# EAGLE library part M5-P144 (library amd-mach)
AMD MACH SERIES
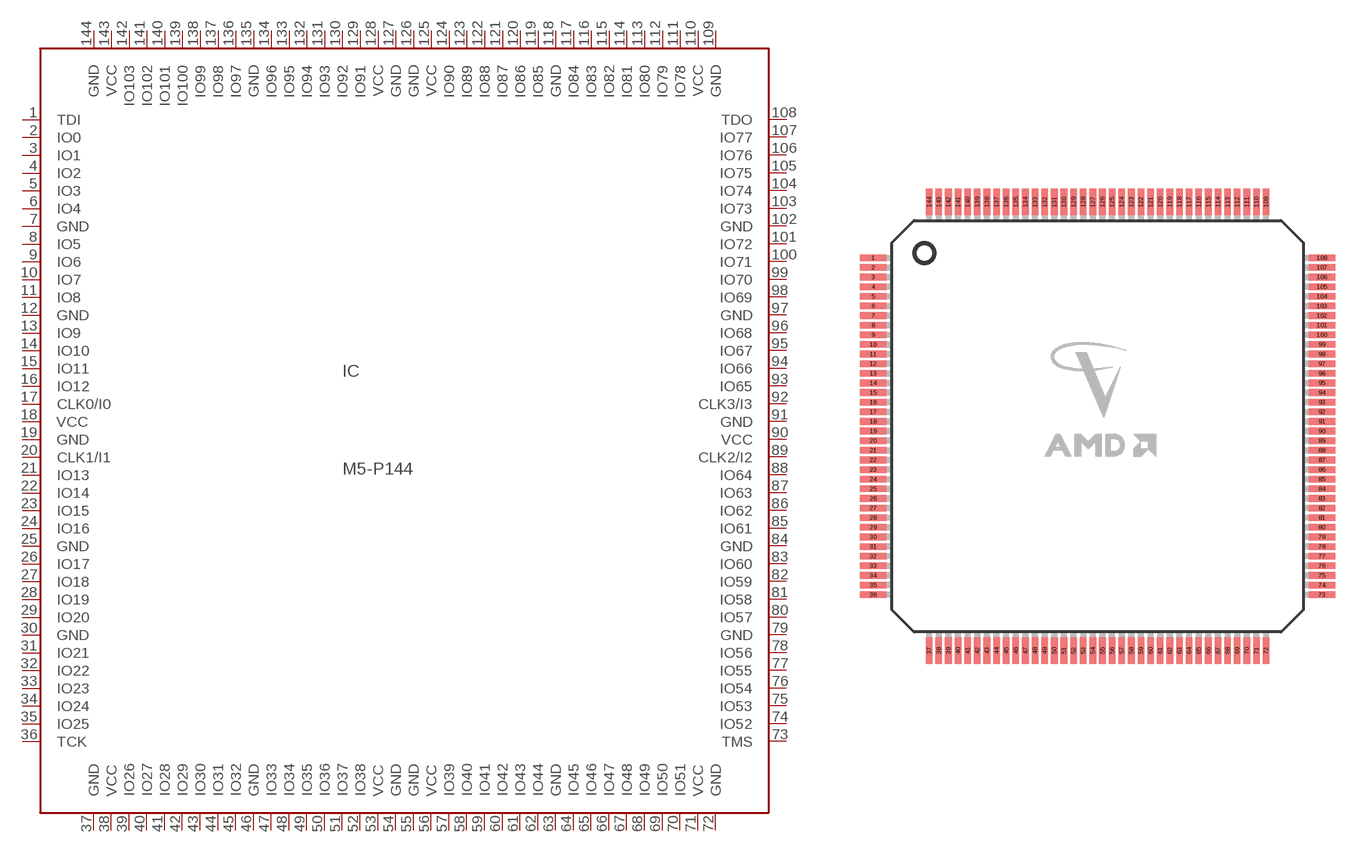
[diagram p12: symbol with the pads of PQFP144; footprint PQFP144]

Designator prefix IC

## M5-P144 (OC_FARNELL: unknown; OC_NEWARK: unknown)  [PQFP144]
1  TDI  in
2  IO0
3  IO1
4  IO2
5  IO3
6  IO4
7  GND  pwr
8  IO5
9  IO6
10  IO7
11  IO8
12  GND  pwr
13  IO9
14  IO10
15  IO11
16  IO12
17  CLK0/I0  in
18  VCC  pwr
19  GND  pwr
20  CLK1/I1  in
21  IO13
22  IO14
23  IO15
24  IO16
25  GND  pwr
26  IO17
27  IO18
28  IO19
29  IO20
30  GND  pwr
31  IO21
32  IO22
33  IO23
34  IO24
35  IO25
36  TCK  in
37  GND  pwr
38  VCC  pwr
39  IO26
40  IO27
41  IO28
42  IO29
43  IO30
44  IO31
45  IO32
46  GND  pwr
47  IO33
48  IO34
49  IO35
50  IO36
51  IO37
52  IO38
53  VCC  pwr
54  GND  pwr
55  GND  pwr
56  VCC  pwr
57  IO39
58  IO40
59  IO41
60  IO42
61  IO43
62  IO44
63  GND  pwr
64  IO45
65  IO46
66  IO47
67  IO48
68  IO49
69  IO50
70  IO51
71  VCC  pwr
72  GND  pwr
73  TMS  in
74  IO52
75  IO53
76  IO54
77  IO55
78  IO56
79  GND  pwr
80  IO57
81  IO58
82  IO59
83  IO60
84  GND  pwr
85  IO61
86  IO62
87  IO63
88  IO64
89  CLK2/I2  in
90  VCC  pwr
91  GND  pwr
92  CLK3/I3  in
93  IO65
94  IO66
95  IO67
96  IO68
97  GND  pwr
98  IO69
99  IO70
100  IO71
101  IO72
102  GND  pwr
103  IO73
104  IO74
105  IO75
106  IO76
107  IO77
108  TDO  out
109  GND  pwr
110  VCC  pwr
111  IO78
112  IO79
113  IO80
114  IO81
115  IO82
116  IO83
117  IO84
118  GND  pwr
119  IO85
120  IO86
121  IO87
122  IO88
123  IO89
124  IO90
125  VCC  pwr
126  GND  pwr
127  GND  pwr
128  VCC  pwr
129  IO91
130  IO92
131  IO93
132  IO94
133  IO95
134  IO96
135  GND  pwr
136  IO97
137  IO98
138  IO99
139  IO100
140  IO101
141  IO102
142  IO103
143  VCC  pwr
144  GND  pwr

## Footprint PQFP144 (pad centres in mm)
PLASTIC QUAD FLAT PACK
smd 1.8 x 0.45: 1 -15.15,11.375; 2 -15.15,10.725; 3 -15.15,10.075; 4 -15.15,9.425; 5 -15.15,8.775; 6 -15.15,8.125; 7 -15.15,7.475; 8 -15.15,6.825; 9 -15.15,6.175; 10 -15.15,5.525; 11 -15.15,4.875; 12 -15.15,4.225; 13 -15.15,3.575; 14 -15.15,2.925; 15 -15.15,2.275; 16 -15.15,1.625; 17 -15.15,0.975; 18 -15.15,0.325; 19 -15.15,-0.325; 20 -15.15,-0.975; 21 -15.15,-1.625; 22 -15.15,-2.275; 23 -15.15,-2.925; 24 -15.15,-3.575; 25 -15.15,-4.225; 26 -15.15,-4.875; 27 -15.15,-5.525; 28 -15.15,-6.175; 29 -15.15,-6.825; 30 -15.15,-7.475; 31 -15.15,-8.125; 32 -15.15,-8.775; 33 -15.15,-9.425; 34 -15.15,-10.075; 35 -15.15,-10.725; 36 -15.15,-11.375; 73 15.15,-11.375; 74 15.15,-10.725; 75 15.15,-10.075; 76 15.15,-9.425; 77 15.15,-8.775; 78 15.15,-8.125; 79 15.15,-7.475; 80 15.15,-6.825; 81 15.15,-6.175; 82 15.15,-5.525; 83 15.15,-4.875; 84 15.15,-4.225; 85 15.15,-3.575; 86 15.15,-2.925; 87 15.15,-2.275; 88 15.15,-1.625; 89 15.15,-0.975; 90 15.15,-0.325; 91 15.15,0.325; 92 15.15,0.975; 93 15.15,1.625; 94 15.15,2.275; 95 15.15,2.925; 96 15.15,3.575; 97 15.15,4.225; 98 15.15,4.875; 99 15.15,5.525; 100 15.15,6.175; 101 15.15,6.825; 102 15.15,7.475; 103 15.15,8.125; 104 15.15,8.775; 105 15.15,9.425; 106 15.15,10.075; 107 15.15,10.725; 108 15.15,11.375
smd 0.45 x 1.8: 37 -11.375,-15.15; 38 -10.725,-15.15; 39 -10.075,-15.15; 40 -9.425,-15.15; 41 -8.775,-15.15; 42 -8.125,-15.15; 43 -7.475,-15.15; 44 -6.825,-15.15; 45 -6.175,-15.15; 46 -5.525,-15.15; 47 -4.875,-15.15; 48 -4.225,-15.15; 49 -3.575,-15.15; 50 -2.925,-15.15; 51 -2.275,-15.15; 52 -1.625,-15.15; 53 -0.975,-15.15; 54 -0.325,-15.15; 55 0.325,-15.15; 56 0.975,-15.15; 57 1.625,-15.15; 58 2.275,-15.15; 59 2.925,-15.15; 60 3.575,-15.15; 61 4.225,-15.15; 62 4.875,-15.15; 63 5.525,-15.15; 64 6.175,-15.15; 65 6.825,-15.15; 66 7.475,-15.15; 67 8.125,-15.15; 68 8.775,-15.15; 69 9.425,-15.15; 70 10.075,-15.15; 71 10.725,-15.15; 72 11.375,-15.15; 109 11.375,15.15; 110 10.725,15.15; 111 10.075,15.15; 112 9.425,15.15; 113 8.775,15.15; 114 8.125,15.15; 115 7.475,15.15; 116 6.825,15.15; 117 6.175,15.15; 118 5.525,15.15; 119 4.875,15.15; 120 4.225,15.15; 121 3.575,15.15; 122 2.925,15.15; 123 2.275,15.15; 124 1.625,15.15; 125 0.975,15.15; 126 0.325,15.15; 127 -0.325,15.15; 128 -0.975,15.15; 129 -1.625,15.15; 130 -2.275,15.15; 131 -2.925,15.15; 132 -3.575,15.15; 133 -4.225,15.15; 134 -4.875,15.15; 135 -5.525,15.15; 136 -6.175,15.15; 137 -6.825,15.15; 138 -7.475,15.15; 139 -8.125,15.15; 140 -8.775,15.15; 141 -9.425,15.15; 142 -10.075,15.15; 143 -10.725,15.15; 144 -11.375,15.15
